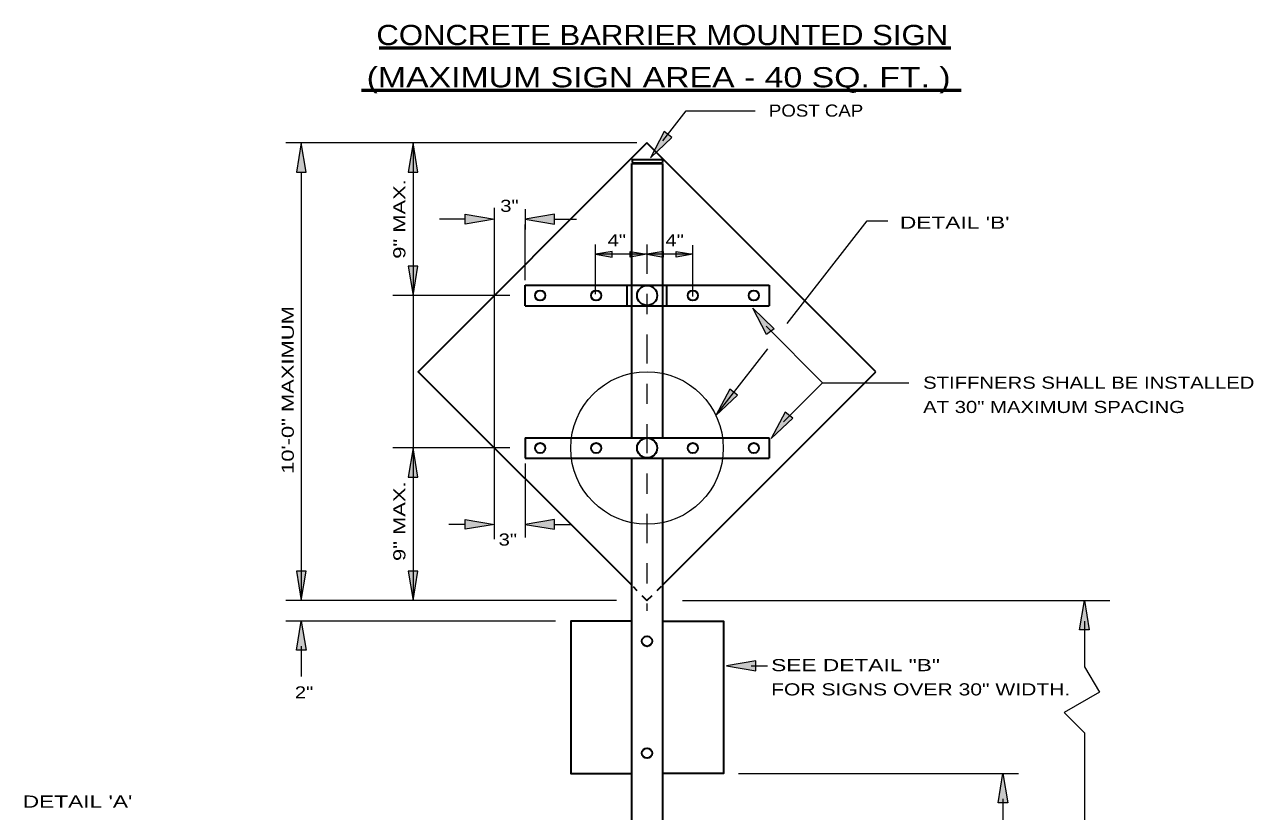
# Model space of a CAD drawing. Extents: x 5332.5 to 5339, y 1824.9 to 1835.1.
# Drawn here: x 5332.9 to 5338.98, y 1831.21 to 1835.1 of the extents above; entities that cross this region are included whole.
import ezdxf
from ezdxf.enums import TextEntityAlignment as Align

# ---------------------------------------------------------------- set-up
doc = ezdxf.new("R2010")
doc.units = 0
doc.header["$LTSCALE"] = 0.024
doc.linetypes.add('LONG_DASH_SHORT_DASH', pattern=[9.9, 6, -1.2, 1.5, -1.2])
for name, color, linetype, lineweight in [('1', 7, 'Continuous', 35), ('10', 7, 'Continuous', 13), ('12', 7, 'Continuous', 53)]:
    doc.layers.add(name, color=color, linetype=linetype, lineweight=lineweight)

msp = doc.modelspace()

# ---------------------------------------------------------------- hatches: boundary and pattern name
at = {"layer": '10'}
for points in [[(5336.102, 1834.542), (5336.064, 1834.571), (5335.996, 1834.441)], [(5334.245, 1834.37), (5334.293, 1834.37), (5334.269, 1834.515)], [(5334.798, 1834.37), (5334.846, 1834.37), (5334.822, 1834.515)], [(5335.08, 1834.113), (5335.08, 1834.162), (5335.225, 1834.138)], [(5335.521, 1834.113), (5335.521, 1834.162), (5335.376, 1834.138)], [(5335.806, 1833.95), (5335.806, 1833.978), (5335.724, 1833.964)], [(5335.896, 1833.95), (5335.896, 1833.978), (5335.978, 1833.964)], [(5336.06, 1833.95), (5336.06, 1833.978), (5335.978, 1833.964)], [(5336.124, 1833.95), (5336.124, 1833.978), (5336.206, 1833.964)], [(5334.846, 1833.905), (5334.798, 1833.905), (5334.822, 1833.76)], [(5336.608, 1833.596), (5336.57, 1833.567), (5336.502, 1833.697)], [(5336.426, 1833.268), (5336.388, 1833.297), (5336.32, 1833.167)], [(5336.7, 1833.154), (5336.662, 1833.183), (5336.594, 1833.053)], [(5334.798, 1832.861), (5334.846, 1832.861), (5334.822, 1833.006)], [(5335.079, 1832.604), (5335.079, 1832.653), (5335.224, 1832.628)], [(5335.521, 1832.604), (5335.521, 1832.653), (5335.376, 1832.628)], [(5334.293, 1832.396), (5334.245, 1832.396), (5334.269, 1832.251)], [(5334.846, 1832.396), (5334.798, 1832.396), (5334.822, 1832.251)], [(5338.167, 1832.106), (5338.118, 1832.106), (5338.143, 1832.251)], [(5334.293, 1832.006), (5334.245, 1832.006), (5334.269, 1832.15)], [(5336.517, 1831.904), (5336.517, 1831.953), (5336.372, 1831.928)], [(5337.764, 1831.251), (5337.716, 1831.251), (5337.74, 1831.396)]]:
    msp.add_hatch(color=256, dxfattribs=at).paths.add_polyline_path(points)

# ---------------------------------------------------------------- linework, layer by layer
at = {"layer": '1'}
for p, q in [((5337.111, 1833.383), (5335.979, 1834.515)), ((5335.904, 1834.417), (5336.055, 1834.417)), ((5335.904, 1834.414), (5336.055, 1834.414)), ((5335.904, 1833.056), (5335.904, 1834.414)), ((5335.905, 1834.433), (5335.905, 1834.42)), ((5336.055, 1834.414), (5336.055, 1833.056)), ((5335.376, 1833.811), (5336.583, 1833.811)), ((5335.376, 1833.71), (5335.376, 1833.811)), ((5335.88, 1833.811), (5335.88, 1833.71)), ((5336.076, 1833.811), (5336.076, 1833.71)), ((5336.583, 1833.811), (5336.583, 1833.71)), ((5335.376, 1833.71), (5336.583, 1833.71)), ((5336.055, 1832.327), (5337.111, 1833.383)), ((5335.376, 1833.056), (5336.583, 1833.056)), ((5335.376, 1833.056), (5335.376, 1832.955)), ((5336.583, 1833.056), (5336.583, 1832.955)), ((5335.376, 1832.955), (5336.583, 1832.955)), ((5335.904, 1831.067), (5335.904, 1832.955)), ((5336.055, 1832.955), (5336.055, 1831.067)), ((5335.91, 1832.321), (5335.929, 1832.301)), ((5336.03, 1832.301), (5336.05, 1832.322)), ((5335.954, 1832.276), (5335.979, 1832.251)), ((5335.979, 1832.251), (5336.005, 1832.276))]:
    msp.add_line(p, q, dxfattribs=at)
for points in [[(5335.979, 1834.515), (5334.847, 1833.383), (5335.904, 1832.327)], [(5335.904, 1834.433), (5336.055, 1834.433), (5336.055, 1834.419)], [(5335.904, 1832.15), (5335.602, 1832.15), (5335.602, 1831.396), (5335.904, 1831.396)], [(5336.055, 1832.15), (5336.357, 1832.15), (5336.357, 1831.396), (5336.055, 1831.396)]]:
    msp.add_lwpolyline(points, dxfattribs=at)
for centre, radius in [((5335.4509, 1833.7603), 0.0252), ((5335.7275, 1833.7603), 0.0252), ((5335.9797, 1833.7606), 0.0495), ((5336.2055, 1833.7603), 0.0252), ((5336.5073, 1833.7603), 0.0252), ((5335.9797, 1833.006), 0.0495), ((5335.4509, 1833.0057), 0.0252), ((5335.7275, 1833.0057), 0.0252), ((5336.2055, 1833.0057), 0.0252), ((5336.5073, 1833.0057), 0.0252), ((5335.9791, 1832.0498), 0.0252), ((5335.9791, 1831.4964), 0.0252)]:
    msp.add_circle(centre, radius, dxfattribs=at)
at = {"layer": '10'}
for p, q in [((5335.929, 1834.515), (5334.193, 1834.515)), ((5334.822, 1834.515), (5334.822, 1832.899)), ((5334.269, 1834.37), (5334.269, 1832.251)), ((5335.225, 1832.555), (5335.225, 1834.194)), ((5335.376, 1834.188), (5335.376, 1834.087)), ((5335.08, 1834.138), (5334.953, 1834.138)), ((5335.376, 1833.836), (5335.376, 1834.112)), ((5335.521, 1834.138), (5335.63, 1834.138)), ((5335.724, 1833.767), (5335.724, 1834.013)), ((5336.206, 1833.964), (5335.724, 1833.964)), ((5336.206, 1833.756), (5336.206, 1834.01)), ((5335.3, 1833.76), (5334.722, 1833.76)), ((5336.568, 1833.608), (5336.847, 1833.329)), ((5336.32, 1833.167), (5336.576, 1833.497)), ((5336.847, 1833.329), (5336.654, 1833.136)), ((5336.846, 1833.329), (5337.275, 1833.329)), ((5335.3, 1833.006), (5334.722, 1833.006)), ((5334.822, 1833.006), (5334.822, 1832.251)), ((5335.376, 1832.93), (5335.376, 1832.564)), ((5335.079, 1832.628), (5334.998, 1832.628)), ((5335.521, 1832.628), (5335.602, 1832.628)), ((5335.828, 1832.251), (5334.193, 1832.251)), ((5336.155, 1832.251), (5338.268, 1832.251)), ((5335.074, 1832.15), (5334.193, 1832.15)), ((5335.527, 1832.15), (5335.074, 1832.15)), ((5338.143, 1832.15), (5338.143, 1831.924)), ((5334.269, 1832.025), (5334.269, 1831.875)), ((5336.494, 1831.928), (5336.575, 1831.928)), ((5338.143, 1831.597), (5338.143, 1830.792)), ((5336.432, 1831.396), (5337.816, 1831.396)), ((5337.74, 1831.27), (5337.74, 1831.044))]:
    msp.add_line(p, q, dxfattribs=at)
at = {"layer": '10', "linetype": 'LONG_DASH_SHORT_DASH'}
msp.add_line((5335.979, 1834.012), (5335.979, 1832.201), dxfattribs=at)
at = {"layer": '10'}
for points in [[(5336.057, 1834.525), (5336.172, 1834.674), (5336.514, 1834.674)], [(5336.673, 1833.621), (5337.068, 1834.13), (5337.17, 1834.13)], [(5338.143, 1831.924), (5338.218, 1831.798), (5338.042, 1831.698), (5338.143, 1831.597)]]:
    msp.add_lwpolyline(points, dxfattribs=at)
for points in [[(5336.102, 1834.542), (5336.064, 1834.571), (5335.996, 1834.441)], [(5334.245, 1834.37), (5334.293, 1834.37), (5334.269, 1834.515)], [(5334.798, 1834.37), (5334.846, 1834.37), (5334.822, 1834.515)], [(5335.08, 1834.113), (5335.08, 1834.162), (5335.225, 1834.138)], [(5335.521, 1834.113), (5335.521, 1834.162), (5335.376, 1834.138)], [(5335.806, 1833.95), (5335.806, 1833.978), (5335.724, 1833.964)], [(5335.896, 1833.95), (5335.896, 1833.978), (5335.978, 1833.964)], [(5336.06, 1833.95), (5336.06, 1833.978), (5335.978, 1833.964)], [(5336.124, 1833.95), (5336.124, 1833.978), (5336.206, 1833.964)], [(5334.846, 1833.905), (5334.798, 1833.905), (5334.822, 1833.76)], [(5336.608, 1833.596), (5336.57, 1833.567), (5336.502, 1833.697)], [(5336.426, 1833.268), (5336.388, 1833.297), (5336.32, 1833.167)], [(5336.7, 1833.154), (5336.662, 1833.183), (5336.594, 1833.053)], [(5334.798, 1832.861), (5334.846, 1832.861), (5334.822, 1833.006)], [(5335.079, 1832.604), (5335.079, 1832.653), (5335.224, 1832.628)], [(5335.521, 1832.604), (5335.521, 1832.653), (5335.376, 1832.628)], [(5334.293, 1832.396), (5334.245, 1832.396), (5334.269, 1832.251)], [(5334.846, 1832.396), (5334.798, 1832.396), (5334.822, 1832.251)], [(5338.167, 1832.106), (5338.118, 1832.106), (5338.143, 1832.251)], [(5334.293, 1832.006), (5334.245, 1832.006), (5334.269, 1832.15)], [(5336.517, 1831.904), (5336.517, 1831.953), (5336.372, 1831.928)], [(5337.764, 1831.251), (5337.716, 1831.251), (5337.74, 1831.396)]]:
    msp.add_lwpolyline(points, close=True, dxfattribs=at)
msp.add_circle((5335.9791, 1833.0057), 0.3773, dxfattribs=at)
at = {"layer": '12'}
for p, q in [((5334.654, 1834.986), (5337.482, 1834.986)), ((5334.567, 1834.776), (5337.533, 1834.776))]:
    msp.add_line(p, q, dxfattribs=at)

# ---------------------------------------------------------------- texts
for s, width, p in [('CONCRETE BARRIER MOUNTED SIGN', 1.15, (5336.0545, 1834.999)), ('(MAXIMUM SIGN AREA - 40 SQ. FT. )', 1.25, (5336.0365, 1834.79))]:
    msp.add_text(s, height=0.1, dxfattribs=dict(at, width=width)).set_placement(p, align=Align.CENTER)
for s, width, p in [('POST CAP', 1.15, (5336.582, 1834.645)), ('3"', 1.25, (5335.253, 1834.174)), ("DETAIL 'B'", 1.4, (5337.23, 1834.091)), ('4"', 1.25, (5335.784, 1834.003)), ('4"', 1.25, (5336.07, 1834.003)), ('STIFFNERS SHALL BE INSTALLED', 1.25, (5337.345, 1833.299)), ('AT 30" MAXIMUM SPACING', 1.25, (5337.345, 1833.179)), ('3"', 1.25, (5335.245, 1832.523)), ('SEE DETAIL "B"', 1.4, (5336.593, 1831.902)), ('FOR SIGNS OVER 30" WIDTH.', 1.3, (5336.593, 1831.782)), ('2"', 1.25, (5334.237, 1831.767)), ("DETAIL 'A'", 1.4, (5332.891, 1831.227))]:
    msp.add_text(s, height=0.06, dxfattribs=dict(at, width=width)).set_placement(p)
at = {"layer": '12', "width": 1.35}
for s, p in [('9" MAX.', (5334.784, 1833.942)), ('10\'-0" MAXIMUM', (5334.232, 1832.878)), ('9" MAX.', (5334.784, 1832.447))]:
    msp.add_text(s, height=0.06, rotation=90, dxfattribs=at).set_placement(p)

doc.saveas('drawing.dxf')
